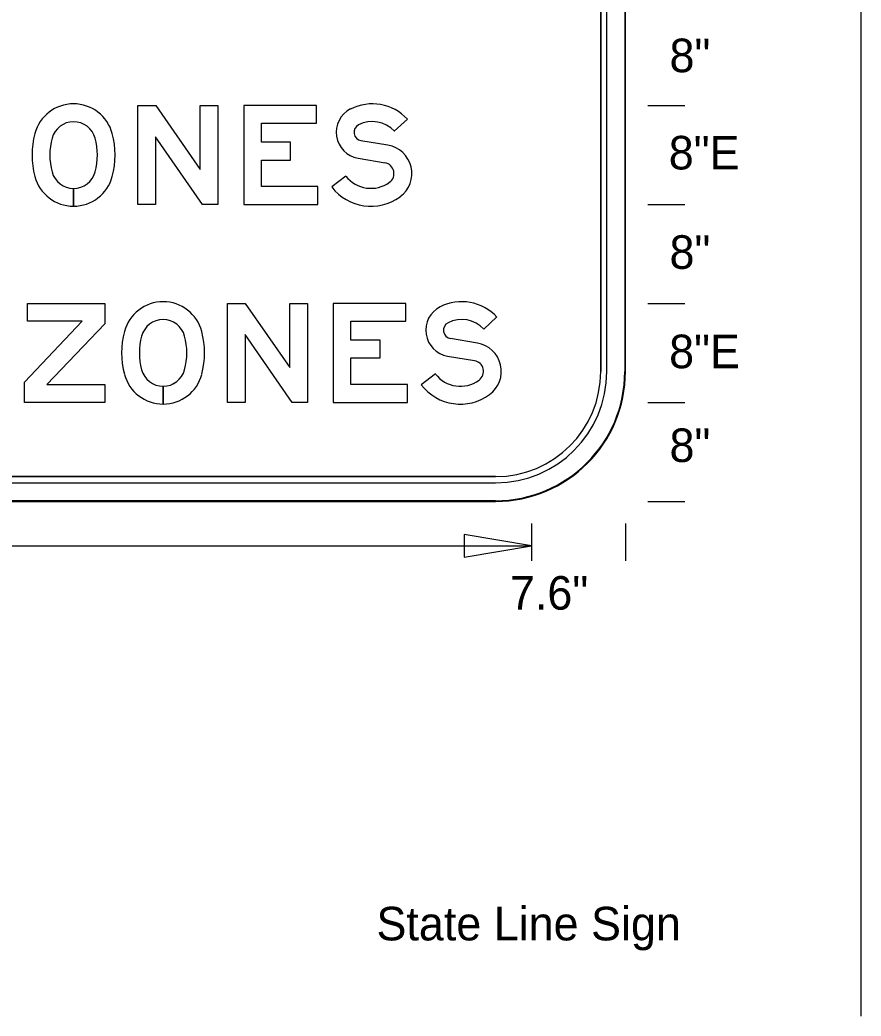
# Model space of a CAD drawing. Extents: x 0 to 770, y 0 to 495.
# Drawn here: x 104.8 to 192.5, y 0 to 103.8 of the extents above; entities that cross this region are included whole.
import ezdxf

# ---------------------------------------------------------------- set-up
doc = ezdxf.new("R2010")
doc.units = 0
for name, color, linetype in [('Dimension', 7, 'Continuous'), ('GSBWFill', 7, 'Continuous'), ('GSColorFill', 7, 'Continuous'), ('GSDims', 7, 'Continuous'), ('GSOutline', 7, 'Continuous'), ('SheetLines_dp', 7, 'Continuous'), ('TextStructures', 7, 'Continuous')]:
    doc.layers.add(name, color=color, linetype=linetype)

msp = doc.modelspace()

# ---------------------------------------------------------------- linework, layer by layer
at = {"layer": 'Dimension'}
msp.add_lwpolyline([(158.13, 49.02), (151.11, 50.21), (151.11, 47.83)], close=True, dxfattribs=at)
at = {"layer": 'GSBWFill'}
for p, q in [((165.35, 132.96), (165.35, 67.2)), ((165.99, 67.2), (165.99, 132.96)), ((167.93, 67.2), (167.93, 132.96)), ((143.82, 92.24), (145.18, 93.51)), ((143.16, 90.79), (140.34, 91.26)), ((140.04, 89.43), (142.85, 88.96)), ((138.76, 87.57), (137.29, 86.44)), ((110.37, 84.43), (110.37, 86.29)), ((110.37, 86.29), (110.37, 84.43)), ((153.16, 71.61), (154.52, 72.88)), ((152.49, 70.16), (149.68, 70.63)), ((149.37, 68.8), (152.18, 68.33)), ((148.1, 66.94), (146.63, 65.81)), ((119.71, 63.8), (119.71, 65.66)), ((119.71, 65.66), (119.71, 63.8)), ((154.39, 56.24), (34.48, 56.24)), ((34.48, 55.6), (154.39, 55.6)), ((34.48, 53.66), (154.39, 53.66))]:
    msp.add_line(p, q, dxfattribs=at)
for points in [[(125.43, 94.92), (125.43, 84.61), (123.83, 84.61), (118.93, 91.67), (118.93, 84.61), (117.08, 84.61), (117.08, 94.92), (118.94, 94.92), (123.57, 88.24), (123.57, 94.92)], [(135.85, 86.47), (129.97, 86.47), (129.97, 89.24), (133.01, 89.24), (133.01, 91.1), (129.97, 91.1), (129.97, 93.07), (135.69, 93.07), (135.69, 94.92), (128.11, 94.92), (128.11, 84.61), (135.85, 84.61)], [(113.62, 65.84), (113.62, 63.98), (105.26, 63.98), (105.26, 66.09), (111.25, 72.44), (105.57, 72.44), (105.57, 74.29), (113.62, 74.29), (113.62, 72.18), (107.58, 65.84)], [(134.77, 74.29), (134.77, 63.98), (133.17, 63.98), (128.27, 71.04), (128.27, 63.98), (126.41, 63.98), (126.41, 74.29), (128.27, 74.29), (132.91, 67.61), (132.91, 74.29)], [(145.18, 65.84), (139.3, 65.84), (139.3, 68.61), (142.35, 68.61), (142.35, 70.47), (139.3, 70.47), (139.3, 72.44), (145.03, 72.44), (145.03, 74.29), (137.45, 74.29), (137.45, 63.98), (145.18, 63.98)]]:
    msp.add_lwpolyline(points, close=True, dxfattribs=at)
for centre, radius, start, end in [((110.37, 90.92), 4.18, 14.9618, 165.0382), ((110.37, 90.92), 2.32, 14.9618, 165.0382), ((114.7, 89.77), 8.66, 165.0382, 194.9618), ((114.7, 89.77), 6.81, 165.0382, 194.9618), ((106.04, 89.77), 6.81, 345.0382, 14.9618), ((106.04, 89.77), 8.66, 345.0382, 14.9618), ((110.37, 88.61), 4.18, 194.9618, 270), ((110.37, 88.61), 2.32, 194.9618, 270), ((110.37, 88.61), 2.32, 270.0127, 345.0382), ((110.37, 88.61), 4.18, 270.0071, 345.0382), ((119.71, 70.29), 4.18, 14.9618, 165.0382), ((119.71, 70.29), 2.32, 14.9618, 165.0382), ((124.04, 69.14), 8.66, 165.0382, 194.9618), ((124.04, 69.14), 6.81, 165.0382, 194.9618), ((115.37, 69.14), 6.81, 345.0382, 14.9618), ((115.37, 69.14), 8.66, 345.0382, 14.9618), ((119.71, 67.98), 4.18, 194.9618, 270), ((119.71, 67.98), 2.32, 194.9618, 270), ((119.71, 67.98), 2.32, 270.0127, 345.0382), ((119.71, 67.98), 4.18, 270.0071, 345.0382), ((154.39, 67.2), 11.6, 270, 0), ((154.39, 67.2), 10.96, 270, 0), ((154.39, 67.2), 13.54, 270, 0)]:
    msp.add_arc(centre, radius, start, end, dxfattribs=at)
for centre, major_axis, start_param, end_param in [((141.52, 90.1), (0, 5), 5.460714, 6.752893), ((140.49, 92.13), (0, 2.73), 0.469708, 2.974193), ((141.52, 90.1), (0, 3.15), 5.460714, 6.752893), ((140.49, 92.13), (0, 0.877), 0.469708, 2.974193), ((142.66, 87.84), (0, 2.99), 3.772058, 6.115786), ((142.66, 87.84), (0, 1.13), 3.772058, 6.115786), ((141.38, 89.59), (0, 3.3), 2.226857, 3.772058), ((141.38, 89.59), (0, 5.16), 2.226857, 3.772058), ((150.85, 69.47), (0, 5), 5.460714, 6.752893), ((149.83, 71.5), (0, 2.73), 0.469708, 2.974193), ((150.85, 69.47), (0, 3.15), 5.460714, 6.752893), ((149.83, 71.5), (0, 0.877), 0.469708, 2.974193), ((151.99, 67.21), (0, 2.99), 3.772058, 6.115786), ((151.99, 67.21), (0, 1.13), 3.772058, 6.115786), ((150.71, 68.96), (0, 3.3), 2.226857, 3.772058), ((150.71, 68.96), (0, 5.16), 2.226857, 3.772058)]:
    msp.add_ellipse(centre, major_axis=major_axis, ratio=0.999994, start_param=start_param, end_param=end_param, dxfattribs=at)
at = {"layer": 'GSColorFill'}
for p, q in [((165.35, 132.96), (165.35, 67.2)), ((165.99, 67.2), (165.99, 132.96)), ((167.86, 132.96), (167.86, 67.2)), ((167.93, 67.2), (167.93, 132.96)), ((167.93, 67.2), (167.93, 132.96)), ((143.82, 92.24), (145.18, 93.51)), ((143.16, 90.79), (140.34, 91.26)), ((140.04, 89.43), (142.85, 88.96)), ((138.76, 87.57), (137.29, 86.44)), ((110.37, 84.43), (110.37, 86.29)), ((110.37, 86.29), (110.37, 84.43)), ((153.16, 71.61), (154.52, 72.88)), ((152.49, 70.16), (149.68, 70.63)), ((149.37, 68.8), (152.18, 68.33)), ((148.1, 66.94), (146.63, 65.81)), ((119.71, 63.8), (119.71, 65.66)), ((119.71, 65.66), (119.71, 63.8)), ((154.39, 56.24), (34.48, 56.24)), ((34.48, 55.6), (154.39, 55.6)), ((154.39, 53.73), (34.48, 53.73)), ((34.48, 53.66), (154.39, 53.66)), ((34.48, 53.66), (154.39, 53.66))]:
    msp.add_line(p, q, dxfattribs=at)
for points in [[(125.43, 94.92), (125.43, 84.61), (123.83, 84.61), (118.93, 91.67), (118.93, 84.61), (117.08, 84.61), (117.08, 94.92), (118.94, 94.92), (123.57, 88.24), (123.57, 94.92)], [(135.85, 86.47), (129.97, 86.47), (129.97, 89.24), (133.01, 89.24), (133.01, 91.1), (129.97, 91.1), (129.97, 93.07), (135.69, 93.07), (135.69, 94.92), (128.11, 94.92), (128.11, 84.61), (135.85, 84.61)], [(113.62, 65.84), (113.62, 63.98), (105.26, 63.98), (105.26, 66.09), (111.25, 72.44), (105.57, 72.44), (105.57, 74.29), (113.62, 74.29), (113.62, 72.18), (107.58, 65.84)], [(134.77, 74.29), (134.77, 63.98), (133.17, 63.98), (128.27, 71.04), (128.27, 63.98), (126.41, 63.98), (126.41, 74.29), (128.27, 74.29), (132.91, 67.61), (132.91, 74.29)], [(145.18, 65.84), (139.3, 65.84), (139.3, 68.61), (142.35, 68.61), (142.35, 70.47), (139.3, 70.47), (139.3, 72.44), (145.03, 72.44), (145.03, 74.29), (137.45, 74.29), (137.45, 63.98), (145.18, 63.98)]]:
    msp.add_lwpolyline(points, close=True, dxfattribs=at)
for centre, radius, start, end in [((110.37, 90.92), 4.18, 14.9618, 165.0382), ((110.37, 90.92), 2.32, 14.9618, 165.0382), ((114.7, 89.77), 8.66, 165.0382, 194.9618), ((114.7, 89.77), 6.81, 165.0382, 194.9618), ((106.04, 89.77), 6.81, 345.0382, 14.9618), ((106.04, 89.77), 8.66, 345.0382, 14.9618), ((110.37, 88.61), 4.18, 194.9618, 270), ((110.37, 88.61), 2.32, 194.9618, 270), ((110.37, 88.61), 2.32, 270.0127, 345.0382), ((110.37, 88.61), 4.18, 270.0071, 345.0382), ((119.71, 70.29), 4.18, 14.9618, 165.0382), ((119.71, 70.29), 2.32, 14.9618, 165.0382), ((124.04, 69.14), 8.66, 165.0382, 194.9618), ((124.04, 69.14), 6.81, 165.0382, 194.9618), ((115.37, 69.14), 6.81, 345.0382, 14.9618), ((115.37, 69.14), 8.66, 345.0382, 14.9618), ((119.71, 67.98), 4.18, 194.9618, 270), ((119.71, 67.98), 2.32, 194.9618, 270), ((119.71, 67.98), 2.32, 270.0127, 345.0382), ((119.71, 67.98), 4.18, 270.0071, 345.0382), ((154.39, 67.2), 13.54, 270, 0), ((154.39, 67.2), 11.6, 270, 0), ((154.39, 67.2), 10.96, 270, 0), ((154.39, 67.2), 13.54, 270, 0), ((154.39, 67.2), 13.47, 270, 0)]:
    msp.add_arc(centre, radius, start, end, dxfattribs=at)
for centre, major_axis, start_param, end_param in [((141.52, 90.1), (0, 5), 5.460714, 6.752893), ((140.49, 92.13), (0, 2.73), 0.469708, 2.974193), ((141.52, 90.1), (0, 3.15), 5.460714, 6.752893), ((140.49, 92.13), (0, 0.877), 0.469708, 2.974193), ((142.66, 87.84), (0, 2.99), 3.772058, 6.115786), ((142.66, 87.84), (0, 1.13), 3.772058, 6.115786), ((141.38, 89.59), (0, 3.3), 2.226857, 3.772058), ((141.38, 89.59), (0, 5.16), 2.226857, 3.772058), ((150.85, 69.47), (0, 5), 5.460714, 6.752893), ((149.83, 71.5), (0, 2.73), 0.469708, 2.974193), ((150.85, 69.47), (0, 3.15), 5.460714, 6.752893), ((149.83, 71.5), (0, 0.877), 0.469708, 2.974193), ((151.99, 67.21), (0, 2.99), 3.772058, 6.115786), ((151.99, 67.21), (0, 1.13), 3.772058, 6.115786), ((150.71, 68.96), (0, 3.3), 2.226857, 3.772058), ((150.71, 68.96), (0, 5.16), 2.226857, 3.772058)]:
    msp.add_ellipse(centre, major_axis=major_axis, ratio=0.999994, start_param=start_param, end_param=end_param, dxfattribs=at)
at = {"layer": 'GSDims'}
for p, q in [((170.25, 94.92), (174.12, 94.92)), ((170.25, 94.92), (174.12, 94.92)), ((170.25, 84.61), (174.12, 84.61)), ((170.25, 84.61), (174.12, 84.61)), ((170.25, 74.29), (174.12, 74.29)), ((170.25, 74.29), (174.12, 74.29)), ((170.25, 63.98), (174.12, 63.98)), ((170.25, 63.98), (174.12, 63.98)), ((170.25, 53.66), (174.12, 53.66)), ((158.13, 51.34), (158.13, 47.47)), ((158.13, 51.34), (158.13, 47.47)), ((167.93, 51.34), (167.93, 47.47)), ((30.74, 49.02), (158.13, 49.02))]:
    msp.add_line(p, q, dxfattribs=at)
at = {"layer": 'GSOutline'}
for p, q in [((165.35, 67.2), (165.35, 132.96)), ((165.99, 67.2), (165.99, 132.96)), ((167.93, 67.2), (167.93, 132.96)), ((143.82, 92.24), (145.18, 93.51)), ((143.16, 90.79), (140.34, 91.26)), ((140.04, 89.43), (142.85, 88.96)), ((138.76, 87.57), (137.29, 86.44)), ((153.16, 71.61), (154.52, 72.88)), ((152.49, 70.16), (149.68, 70.63)), ((149.37, 68.8), (152.18, 68.33)), ((148.1, 66.94), (146.63, 65.81)), ((34.48, 56.24), (154.39, 56.24)), ((34.48, 55.6), (154.39, 55.6)), ((34.48, 53.66), (154.39, 53.66))]:
    msp.add_line(p, q, dxfattribs=at)
for points in [[(125.43, 94.92), (125.43, 84.61), (123.83, 84.61), (118.93, 91.67), (118.93, 84.61), (117.08, 84.61), (117.08, 94.92), (118.94, 94.92), (123.57, 88.24), (123.57, 94.92)], [(135.85, 86.47), (129.97, 86.47), (129.97, 89.24), (133.01, 89.24), (133.01, 91.1), (129.97, 91.1), (129.97, 93.07), (135.69, 93.07), (135.69, 94.92), (128.11, 94.92), (128.11, 84.61), (135.85, 84.61)], [(113.62, 65.84), (113.62, 63.98), (105.26, 63.98), (105.26, 66.09), (111.25, 72.44), (105.57, 72.44), (105.57, 74.29), (113.62, 74.29), (113.62, 72.18), (107.58, 65.84)], [(134.77, 74.29), (134.77, 63.98), (133.17, 63.98), (128.27, 71.04), (128.27, 63.98), (126.41, 63.98), (126.41, 74.29), (128.27, 74.29), (132.91, 67.61), (132.91, 74.29)], [(145.18, 65.84), (139.3, 65.84), (139.3, 68.61), (142.35, 68.61), (142.35, 70.47), (139.3, 70.47), (139.3, 72.44), (145.03, 72.44), (145.03, 74.29), (137.45, 74.29), (137.45, 63.98), (145.18, 63.98)]]:
    msp.add_lwpolyline(points, close=True, dxfattribs=at)
for centre, radius, start, end in [((110.37, 90.92), 4.18, 14.9618, 165.0382), ((110.37, 90.92), 2.32, 14.9618, 165.0382), ((114.7, 89.77), 8.66, 165.0382, 194.9618), ((114.7, 89.77), 6.81, 165.0382, 194.9618), ((106.04, 89.77), 6.81, 345.0382, 14.9618), ((106.04, 89.77), 8.66, 345.0382, 14.9618), ((110.37, 88.61), 4.18, 194.9618, 345.0382), ((110.37, 88.61), 2.32, 194.9618, 345.0382), ((119.71, 70.29), 4.18, 14.9618, 165.0382), ((119.71, 70.29), 2.32, 14.9618, 165.0382), ((124.04, 69.14), 8.66, 165.0382, 194.9618), ((124.04, 69.14), 6.81, 165.0382, 194.9618), ((115.37, 69.14), 6.81, 345.0382, 14.9618), ((115.37, 69.14), 8.66, 345.0382, 14.9618), ((119.71, 67.98), 4.18, 194.9618, 345.0382), ((119.71, 67.98), 2.32, 194.9618, 345.0382), ((154.39, 67.2), 11.6, 270, 0), ((154.39, 67.2), 10.96, 270, 0), ((154.39, 67.2), 13.54, 270, 0)]:
    msp.add_arc(centre, radius, start, end, dxfattribs=at)
for centre, major_axis, start_param, end_param in [((141.52, 90.1), (0, 5), 5.460714, 6.752893), ((140.49, 92.13), (0, 2.73), 0.469708, 2.974193), ((141.52, 90.1), (0, 3.15), 5.460714, 6.752893), ((140.49, 92.13), (0, 0.877), 0.469708, 2.974193), ((142.66, 87.84), (0, 2.99), 3.772058, 6.115786), ((142.66, 87.84), (0, 1.13), 3.772058, 6.115786), ((141.38, 89.59), (0, 3.3), 2.226857, 3.772058), ((141.38, 89.59), (0, 5.16), 2.226857, 3.772058), ((150.85, 69.47), (0, 5), 5.460714, 6.752893), ((149.83, 71.5), (0, 2.73), 0.469708, 2.974193), ((150.85, 69.47), (0, 3.15), 5.460714, 6.752893), ((149.83, 71.5), (0, 0.877), 0.469708, 2.974193), ((151.99, 67.21), (0, 2.99), 3.772058, 6.115786), ((151.99, 67.21), (0, 1.13), 3.772058, 6.115786), ((150.71, 68.96), (0, 3.3), 2.226857, 3.772058), ((150.71, 68.96), (0, 5.16), 2.226857, 3.772058)]:
    msp.add_ellipse(centre, major_axis=major_axis, ratio=0.999994, start_param=start_param, end_param=end_param, dxfattribs=at)
at = {"layer": 'SheetLines_dp'}
msp.add_line((192.5, 0), (192.5, 495), dxfattribs=at)

# ---------------------------------------------------------------- texts
at = {"layer": 'TextStructures'}
for s, p in [('8"', (172.52, 98.4)), ('8"E', (172.44, 88.26)), ('8"', (172.52, 77.9)), ('8"E', (172.48, 67.54)), ('8"', (172.52, 57.76)), ('7.6"', (155.88, 42.37)), ('State Line Sign', (141.96, 7.89))]:
    msp.add_text(s, height=3.5, dxfattribs=at).set_placement(p)

doc.saveas('drawing.dxf')
